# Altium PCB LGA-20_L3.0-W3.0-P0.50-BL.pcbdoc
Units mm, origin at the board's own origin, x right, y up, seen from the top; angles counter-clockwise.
Board outline 16.4 x 16.57 mm, 2 copper layers (Top Layer, Bottom Layer), stack 0 mm thick; 1 components, 0 nets, 20 pads, 0 vias.
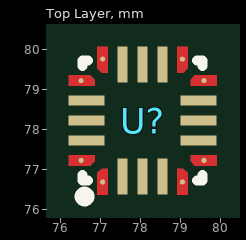
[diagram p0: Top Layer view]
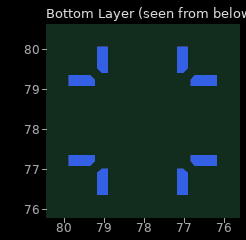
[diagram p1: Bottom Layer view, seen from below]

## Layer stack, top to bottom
Top Layer: signal copper (thickness not stored)
Bottom Layer: signal copper (thickness not stored)

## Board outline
86.25,69.85 69.85,69.85 69.85,86.42 86.25,86.42

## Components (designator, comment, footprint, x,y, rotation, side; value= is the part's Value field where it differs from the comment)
U? "" LGA-20_L3.0-W3.0-P0.50-BL 78.05,78.22 r0 top

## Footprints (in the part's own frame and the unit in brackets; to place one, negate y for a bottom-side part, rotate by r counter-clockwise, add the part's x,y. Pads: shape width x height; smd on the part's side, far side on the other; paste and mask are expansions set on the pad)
LGA-20_L3.0-W3.0-P0.50-BL [mm]
  round 0.127 smd: 1(-0.996,-1.536) 5(0.997,-1.536) 6(1.536,-0.997) 10(1.536,0.997) 11(0.997,1.536) 15(-0.997,1.536) 16(-1.536,0.997) 20(-1.536,-0.997)
  rect 0.25x0.9 smd paste+0 mask+0.05: 2(-0.5,-1.4) 3(0,-1.4) 4(0.5,-1.4) 12(0.5,1.4) 13(0,1.4) 14(-0.5,1.4)
  rect 0.9x0.25 smd paste+0 mask+0.05: 7(1.4,-0.5) 8(1.4,0) 9(1.4,0.5) 17(-1.4,0.5) 18(-1.4,0) 19(-1.4,-0.5)
  Top Layer region: -1.13,-1.85 -0.87,-1.85 -0.87,-1.2 -1.02,-1.2 -1.13,-1.31
  Top Layer region: 1.85,-1.13 1.85,-0.87 1.2,-0.87 1.2,-1.02 1.31,-1.13
  Top Layer region: 1.13,1.85 0.87,1.85 0.87,1.2 1.02,1.2 1.13,1.31
  Top Layer region: -1.85,1.13 -1.85,0.87 -1.2,0.87 -1.2,1.02 -1.31,1.13
  Top Layer region: -1.85,-1.13 -1.85,-0.87 -1.2,-0.87 -1.2,-1.02 -1.31,-1.13
  Top Layer region: -1.13,1.85 -0.87,1.85 -0.87,1.2 -1.02,1.2 -1.13,1.31
  Top Layer region: 1.85,1.13 1.85,0.87 1.2,0.87 1.2,1.02 1.31,1.13
  Top Layer region: 1.13,-1.85 0.87,-1.85 0.87,-1.2 1.02,-1.2 1.13,-1.31
  Bottom Layer region: -1.13,-1.85 -0.87,-1.85 -0.87,-1.2 -1.02,-1.2 -1.13,-1.31
  Bottom Layer region: 1.85,-1.13 1.85,-0.87 1.2,-0.87 1.2,-1.02 1.31,-1.13
  Bottom Layer region: 1.13,1.85 0.87,1.85 0.87,1.2 1.02,1.2 1.13,1.31
  Bottom Layer region: -1.85,1.13 -1.85,0.87 -1.2,0.87 -1.2,1.02 -1.31,1.13
  Bottom Layer region: -1.85,-1.13 -1.85,-0.87 -1.2,-0.87 -1.2,-1.02 -1.31,-1.13
  Bottom Layer region: -1.13,1.85 -0.87,1.85 -0.87,1.2 -1.02,1.2 -1.13,1.31
  Bottom Layer region: 1.85,1.13 1.85,0.87 1.2,0.87 1.2,1.02 1.31,1.13
  Bottom Layer region: 1.13,-1.85 0.87,-1.85 0.87,-1.2 1.02,-1.2 1.13,-1.31
  Multi-Layer region: -1.13,-1.85 -0.87,-1.85 -0.87,-1.2 -1.02,-1.2 -1.13,-1.31
  Multi-Layer region: 1.85,-1.13 1.85,-0.87 1.2,-0.87 1.2,-1.02 1.31,-1.13
  Multi-Layer region: 1.13,1.85 0.87,1.85 0.87,1.2 1.02,1.2 1.13,1.31
  Multi-Layer region: -1.85,1.13 -1.85,0.87 -1.2,0.87 -1.2,1.02 -1.31,1.13
  Multi-Layer region: -1.85,-1.13 -1.85,-0.87 -1.2,-0.87 -1.2,-1.02 -1.31,-1.13
  Multi-Layer region: -1.13,1.85 -0.87,1.85 -0.87,1.2 -1.02,1.2 -1.13,1.31
  Multi-Layer region: 1.85,1.13 1.85,0.87 1.2,0.87 1.2,1.02 1.31,1.13
  Multi-Layer region: 1.13,-1.85 0.87,-1.85 0.87,-1.2 1.02,-1.2 1.13,-1.31
  silkscreen extent -1.57,-2.02 1.5,1.5

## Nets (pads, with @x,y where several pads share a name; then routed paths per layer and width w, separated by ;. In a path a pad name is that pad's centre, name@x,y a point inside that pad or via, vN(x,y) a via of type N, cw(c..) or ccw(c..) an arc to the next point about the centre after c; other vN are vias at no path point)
pads on no net: U?.1 U?.2 U?.3 U?.4 U?.5 U?.6 U?.7 U?.8 U?.9 U?.10 U?.11 U?.12 U?.13 U?.14 U?.15 U?.16 U?.17 U?.18 U?.19 U?.20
